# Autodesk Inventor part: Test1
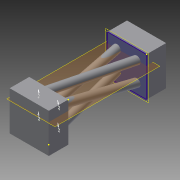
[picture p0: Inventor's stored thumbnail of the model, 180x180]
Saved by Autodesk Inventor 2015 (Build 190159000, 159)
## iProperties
Created: 2016-12
Part Number: Test1
Material: Generisch
Document SubType Name: Modeling
Designer: Andreas
Density: 1 g/cm^3
Appearance: Vorgabe
Author: Andreas
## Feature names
1. Extrusion1
2. Sweeping1
3. Sweeping2
4. Sweeping3
5. Sweeping4
6. Extrusion2
## Parameters: d2 = 5 mm, d3 = 0, d4 = 2 mm, d5 = 2 mm, d6 = 2 mm, d7 = 2 mm, d9 = 2 mm, d10 = 2 mm, d11 = 2 mm, d12 = 2 mm, d14 = -2.5 mm, d15 = 0, d16 = 0, d17 = -2.5 mm, d18 = 0, d19 = 0, d20 = -2.5 mm, d21 = 0, d22 = 0, d23 = -2.5 mm, d24 = 0, d25 = 0, d26 = 5 mm, d27 = 0
